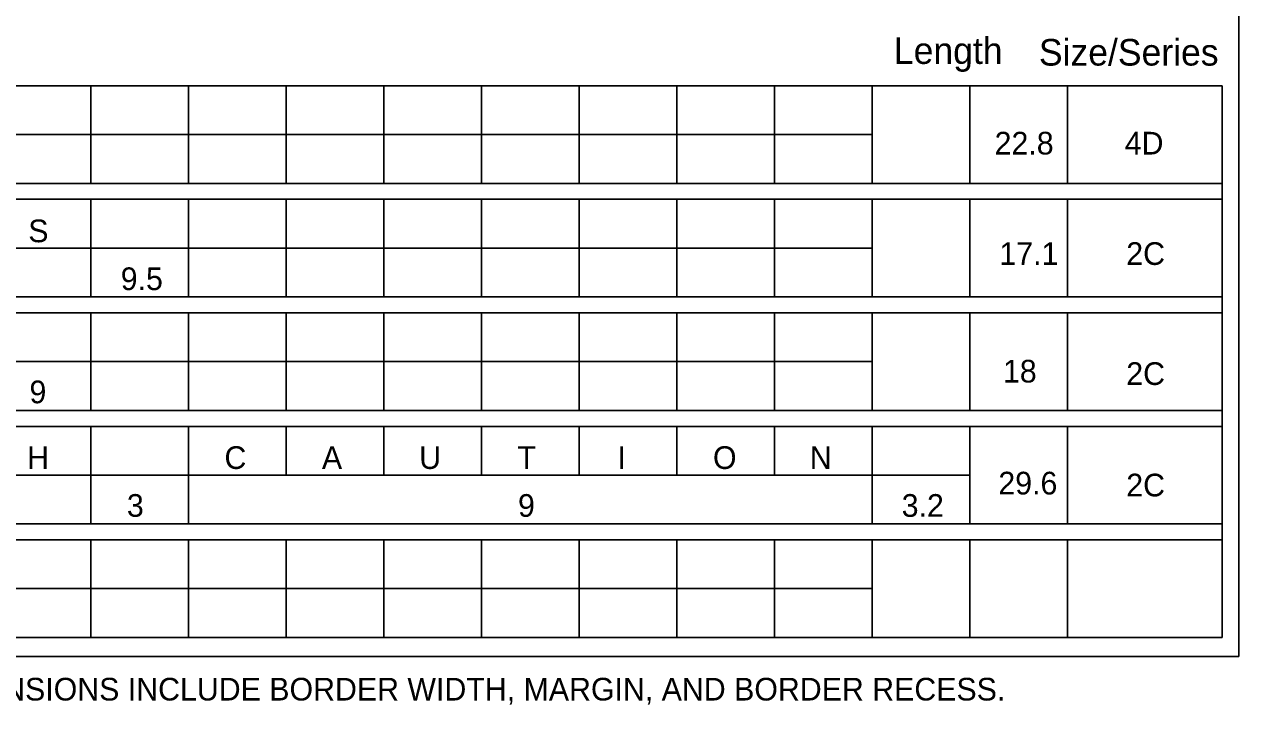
# Model space of a CAD drawing. Extents: x 53068 to 53703, y 9291 to 9710.
# Drawn here: x 53241.3 to 53391.3, y 9329.5 to 9413.5 of the extents above; entities that cross this region are included whole.
import ezdxf

# ---------------------------------------------------------------- set-up
doc = ezdxf.new("R2010")
doc.units = 0
for name, color, linetype in [('GSDims', 7, 'Continuous'), ('SheetLines_dp', 7, 'Continuous'), ('SumBoxLinesMin_dp', 7, 'Continuous'), ('TextNotes', 7, 'Continuous')]:
    doc.layers.add(name, color=color, linetype=linetype)

msp = doc.modelspace()

# ---------------------------------------------------------------- linework, layer by layer
at = {"layer": 'SheetLines_dp'}
for p in [(53391.35, 9519.5), (53089.8, 9335.4)]:
    msp.add_line(p, (53391.35, 9335.4), dxfattribs=at)
at = {"layer": 'SumBoxLinesMin_dp'}
for p, q in [((53092.7, 9405.87), (53389.3, 9405.87)), ((53249.55, 9405.87), (53249.55, 9393.83)), ((53261.62, 9405.87), (53261.62, 9393.83)), ((53273.68, 9405.87), (53273.68, 9393.83)), ((53285.75, 9405.87), (53285.75, 9393.83)), ((53297.81, 9405.87), (53297.81, 9393.83)), ((53309.88, 9405.87), (53309.88, 9393.83)), ((53321.94, 9405.87), (53321.94, 9393.83)), ((53334.01, 9405.87), (53334.01, 9393.83)), ((53346.08, 9405.87), (53346.08, 9393.83)), ((53358.14, 9405.87), (53358.14, 9393.83)), ((53370.21, 9405.87), (53370.21, 9393.83)), ((53389.3, 9337.77), (53389.3, 9405.87)), ((53092.7, 9399.85), (53346.08, 9399.85)), ((53092.7, 9393.83), (53389.3, 9393.83)), ((53092.7, 9391.86), (53389.3, 9391.86)), ((53249.55, 9391.86), (53249.55, 9379.81)), ((53261.62, 9391.86), (53261.62, 9379.81)), ((53273.68, 9391.86), (53273.68, 9379.81)), ((53285.75, 9391.86), (53285.75, 9379.81)), ((53297.81, 9391.86), (53297.81, 9379.81)), ((53309.88, 9391.86), (53309.88, 9379.81)), ((53321.94, 9391.86), (53321.94, 9379.81)), ((53334.01, 9391.86), (53334.01, 9379.81)), ((53346.08, 9391.86), (53346.08, 9379.81)), ((53358.14, 9391.86), (53358.14, 9379.81)), ((53370.21, 9391.86), (53370.21, 9379.81)), ((53092.7, 9385.83), (53346.08, 9385.83)), ((53092.7, 9379.81), (53389.3, 9379.81)), ((53092.7, 9377.85), (53389.3, 9377.85)), ((53249.55, 9377.85), (53249.55, 9365.79)), ((53261.62, 9377.85), (53261.62, 9365.79)), ((53273.68, 9377.85), (53273.68, 9365.79)), ((53285.75, 9377.85), (53285.75, 9365.79)), ((53297.81, 9377.85), (53297.81, 9365.79)), ((53309.88, 9377.85), (53309.88, 9365.79)), ((53321.94, 9377.85), (53321.94, 9365.79)), ((53334.01, 9377.85), (53334.01, 9365.79)), ((53346.08, 9377.85), (53346.08, 9365.79)), ((53358.14, 9377.85), (53358.14, 9365.79)), ((53370.21, 9377.85), (53370.21, 9365.79)), ((53092.7, 9371.82), (53346.08, 9371.82)), ((53092.7, 9365.79), (53389.3, 9365.79)), ((53092.7, 9363.83), (53389.3, 9363.83)), ((53249.55, 9363.83), (53249.55, 9351.78)), ((53261.62, 9363.83), (53261.62, 9351.78)), ((53273.68, 9363.83), (53273.68, 9357.81)), ((53285.75, 9363.83), (53285.75, 9357.81)), ((53297.81, 9363.83), (53297.81, 9357.81)), ((53309.88, 9363.83), (53309.88, 9357.81)), ((53321.94, 9363.83), (53321.94, 9357.81)), ((53334.01, 9363.83), (53334.01, 9357.81)), ((53346.08, 9363.83), (53346.08, 9351.78)), ((53358.14, 9363.83), (53358.14, 9351.78)), ((53370.21, 9363.83), (53370.21, 9351.78)), ((53092.7, 9357.81), (53358.14, 9357.81)), ((53092.7, 9351.78), (53389.3, 9351.78)), ((53092.7, 9349.82), (53389.3, 9349.82)), ((53249.55, 9349.82), (53249.55, 9337.77)), ((53261.62, 9349.82), (53261.62, 9337.77)), ((53273.68, 9349.82), (53273.68, 9337.77)), ((53285.75, 9349.82), (53285.75, 9337.77)), ((53297.81, 9349.82), (53297.81, 9337.77)), ((53309.88, 9349.82), (53309.88, 9337.77)), ((53321.94, 9349.82), (53321.94, 9337.77)), ((53334.01, 9349.82), (53334.01, 9337.77)), ((53346.08, 9349.82), (53346.08, 9337.77)), ((53358.14, 9349.82), (53358.14, 9337.77)), ((53370.21, 9349.82), (53370.21, 9337.77)), ((53092.7, 9343.79), (53346.08, 9343.79)), ((53092.7, 9337.77), (53389.3, 9337.77))]:
    msp.add_line(p, q, dxfattribs=at)

# ---------------------------------------------------------------- texts
at = {"layer": 'GSDims'}
for s, height, p in [('Length', 3.281, (53348.76, 9408.57)), ('Size/Series', 3.2807, (53366.67, 9408.37)), ('22.8', 2.8, (53361.2, 9397.39)), ('4D', 2.8, (53377.27, 9397.39)), ('S', 2.8, (53241.84, 9386.56)), ('17.1', 2.8, (53361.79, 9383.76)), ('2C', 2.8, (53377.46, 9383.76)), ('9.5', 2.8, (53253.26, 9380.65)), ('18', 2.8, (53362.23, 9369.24)), ('2C', 2.8, (53377.46, 9368.94)), ('9', 2.8, (53241.99, 9366.68)), ('H', 2.8, (53241.7, 9358.57)), ('C', 2.8, (53266.07, 9358.57)), ('A', 2.8, (53278.11, 9358.57)), ('U', 2.8, (53290.12, 9358.57)), ('T', 2.8, (53302.25, 9358.57)), ('I', 2.8, (53314.61, 9358.57)), ('O', 2.8, (53326.41, 9358.57)), ('N', 2.8, (53338.37, 9358.57)), ('29.6', 2.8, (53361.66, 9355.42)), ('2C', 2.8, (53377.46, 9355.18)), ('3', 2.8, (53254.02, 9352.66)), ('9', 2.8, (53302.33, 9352.66)), ('3.2', 2.8, (53349.72, 9352.66))]:
    msp.add_text(s, height=height, dxfattribs=at).set_placement(p)
at = {"layer": 'TextNotes'}
msp.add_text('NOTE:  WIDTH - HORIZONTAL SPACING DIMENSIONS ARE IN INCHES.  END DIMENSIONS INCLUDE BORDER WIDTH, MARGIN, AND BORDER RECESS.', height=2.8, dxfattribs=at).set_placement((53092.7, 9329.98))

doc.saveas('drawing.dxf')
